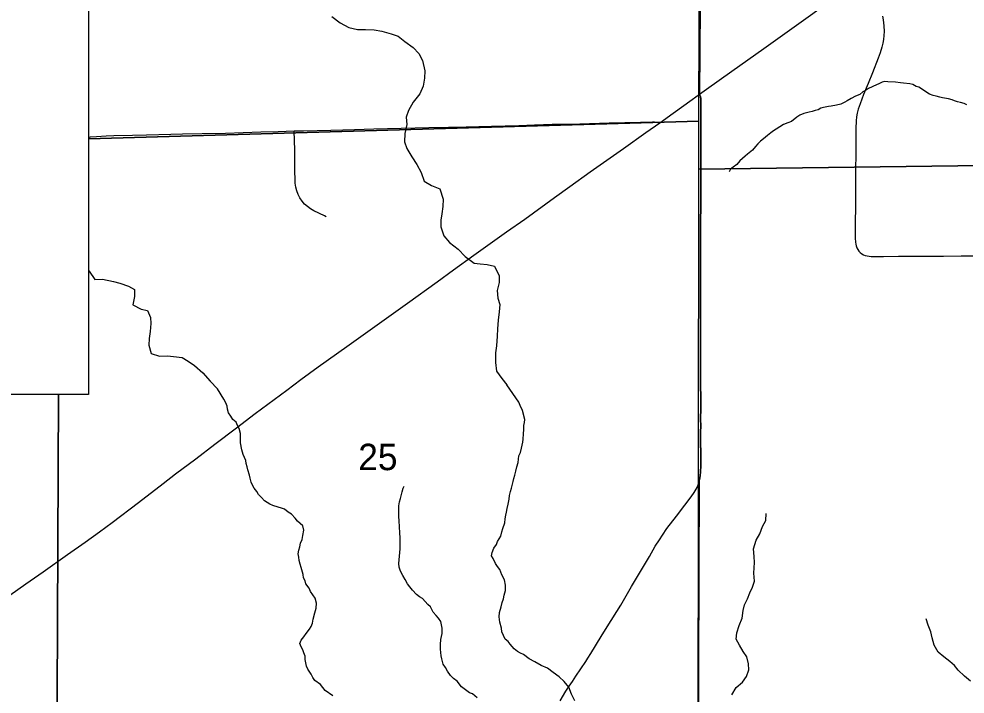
# Model space of a CAD drawing. Extents: x 0 to 34, y 0 to 22.
# Drawn here: x 4.694 to 6.195, y 16.396 to 17.466 of the extents above; entities that cross this region are included whole.
import ezdxf

# ---------------------------------------------------------------- set-up
doc = ezdxf.new("R2010")
doc.units = 0
for name, color, linetype in [('GM_X_County_Road', 7, 'Continuous'), ('GM_X_Minor_River', 7, 'Continuous'), ('GM_X_Section', 7, 'Continuous'), ('GM_X_Section_Text', 7, 'Continuous'), ('GM_X_State_Route', 7, 'Continuous'), ('GM_X_Township_Road', 7, 'Continuous'), ('SH_Text', 7, 'Continuous')]:
    doc.layers.add(name, color=color, linetype=linetype)

msp = doc.modelspace()

# ---------------------------------------------------------------- linework, layer by layer
at = {"layer": 'GM_X_County_Road'}
for points in [[(5.7756, 17.0016), (5.7756, 17.0136), (5.7756, 17.0291), (5.7756, 17.0416), (5.7756, 17.054), (5.7754, 17.0788), (5.7754, 17.0981), (5.7753, 17.1111), (5.7755, 17.1315), (5.7757, 17.1502), (5.776, 17.1626), (5.776, 17.1751), (5.7759, 17.1968), (5.7759, 17.2123), (5.7759, 17.2309), (5.7758, 17.2558), (5.776, 17.2689), (5.7761, 17.283), (5.7762, 17.309), (5.7759, 17.3389), (5.7754, 17.3427), (5.7746, 17.345), (5.7738, 17.3471)], [(5.5525, 16.3849), (5.5618, 16.4), (5.5671, 16.408), (5.5719, 16.4155), (5.5772, 16.4237), (5.5932, 16.447), (5.5965, 16.4522), (5.6015, 16.4601), (5.6175, 16.4866), (5.6272, 16.5024), (5.6488, 16.5368), (5.6658, 16.5659), (5.685, 16.5978), (5.6942, 16.6139), (5.7034, 16.6299), (5.71, 16.6402), (5.7147, 16.6478), (5.7219, 16.6579), (5.7369, 16.6776), (5.7504, 16.695), (5.7605, 16.7083), (5.7654, 16.715), (5.7685, 16.7204), (5.7699, 16.7232), (5.7722, 16.7291), (5.7734, 16.7337), (5.7738, 16.7352), (5.7749, 16.7414), (5.7756, 16.7476), (5.7759, 16.757), (5.7758, 16.7756), (5.7758, 16.7819), (5.7755, 16.7899), (5.7755, 16.7965), (5.7757, 16.8028), (5.7756, 16.8095), (5.7758, 16.8214), (5.7756, 16.8299), (5.7756, 16.8369), (5.7758, 16.8428), (5.7758, 16.849), (5.7758, 16.8614), (5.7757, 16.8893), (5.7757, 16.9111), (5.7755, 16.9546), (5.7756, 17.0016)]]:
    msp.add_lwpolyline(points, dxfattribs=at)
at = {"layer": 'GM_X_Minor_River'}
for points in [[(5.1905, 17.4701), (5.2034, 17.4604), (5.2171, 17.4529), (5.2311, 17.4495), (5.2436, 17.4496), (5.2576, 17.4493), (5.2697, 17.4471), (5.2845, 17.443), (5.2955, 17.4389), (5.3062, 17.4306), (5.3195, 17.4212), (5.3283, 17.4114), (5.3344, 17.4008), (5.3379, 17.3841), (5.3372, 17.3724), (5.335, 17.3599), (5.3301, 17.3477), (5.3196, 17.3344), (5.3121, 17.3214), (5.308, 17.3108), (5.3092, 17.299), (5.3059, 17.2846), (5.3055, 17.2717), (5.3094, 17.2611), (5.3174, 17.2475), (5.3254, 17.2354), (5.3319, 17.2229), (5.3366, 17.2093), (5.3483, 17.2022), (5.3616, 17.1969), (5.367, 17.1806), (5.3663, 17.1689), (5.3649, 17.1575), (5.3634, 17.1472), (5.3635, 17.1366), (5.3681, 17.1226), (5.3772, 17.112), (5.3906, 17.1015), (5.4016, 17.0894), (5.4161, 17.0793), (5.4259, 17.0782), (5.4369, 17.0771), (5.4483, 17.0742), (5.4559, 17.059), (5.4556, 17.0484), (5.4527, 17.0359), (5.4539, 17.0234), (5.4566, 17.0135), (5.4559, 17.0021), (5.4541, 16.9885), (5.4534, 16.9748), (5.4527, 16.9631), (5.4516, 16.9479), (5.4502, 16.9369), (5.4499, 16.9213), (5.4518, 16.9077), (5.4599, 16.8963), (5.4682, 16.8862)], [(6.198, 17.33), (6.1934, 17.3323), (6.1877, 17.3341), (6.1831, 17.3352), (6.1785, 17.3366), (6.1743, 17.3381), (6.1686, 17.3399), (6.159, 17.3413), (6.1552, 17.3424), (6.1491, 17.3442), (6.1445, 17.3449), (6.1388, 17.3471), (6.1216, 17.3583), (6.1174, 17.3593), (6.112, 17.3623), (6.1074, 17.3634), (6.0975, 17.3648), (6.0926, 17.3651), (6.0846, 17.3661), (6.0724, 17.3667), (6.0678, 17.367), (6.0636, 17.3662), (6.0584, 17.3635), (6.0546, 17.3619), (6.0417, 17.3561), (6.0372, 17.353), (6.033, 17.3506), (6.0281, 17.3468), (6.0213, 17.344), (6.0142, 17.3405), (6.0081, 17.3366), (6.0043, 17.3347), (5.9979, 17.3315), (5.9911, 17.3299), (5.9827, 17.3283), (5.9782, 17.3275), (5.9706, 17.3259), (5.9664, 17.3247), (5.9619, 17.3223), (5.9574, 17.3211), (5.9524, 17.3195), (5.9479, 17.3187), (5.9433, 17.3175), (5.9392, 17.3163), (5.9331, 17.314), (5.9282, 17.3105), (5.9196, 17.3039), (5.9139, 17.3019), (5.9067, 17.2988), (5.8954, 17.2918), (5.8912, 17.2891), (5.8867, 17.286), (5.8814, 17.2817), (5.8754, 17.2763), (5.8705, 17.2725), (5.8664, 17.2686), (5.8623, 17.264), (5.8578, 17.2583), (5.8499, 17.2521), (5.8461, 17.2486), (5.8378, 17.2413), (5.833, 17.2355)], [(5.833, 17.2355), (5.8273, 17.2316), (5.8228, 17.2282), (5.8209, 17.224)], [(4.804, 17.0684), (4.8052, 17.0662), (4.814, 17.053), (4.8265, 17.0538), (4.844, 17.0501), (4.8538, 17.0475), (4.8675, 17.0427), (4.8774, 17.0371), (4.8774, 17.0261), (4.8745, 17.0131), (4.8877, 17.006), (4.8976, 17.0038), (4.9026, 16.9928), (4.903, 16.9833), (4.9023, 16.9704), (4.9005, 16.9594), (4.8998, 16.9488), (4.9037, 16.9356), (4.9169, 16.9315), (4.9298, 16.9319), (4.9393, 16.9312), (4.9526, 16.9294), (4.9621, 16.9238), (4.9723, 16.9166), (4.9856, 16.9049), (4.9975, 16.8917), (5.0087, 16.8795)], [(5.1917, 16.3926), (5.1799, 16.4014), (5.1722, 16.4109), (5.1634, 16.417), (5.16, 16.4219), (5.1573, 16.4272), (5.1523, 16.4352), (5.15, 16.4398), (5.1481, 16.4504), (5.1481, 16.4558), (5.1458, 16.4611), (5.1442, 16.4656), (5.1415, 16.4702), (5.1396, 16.4755), (5.1415, 16.4809), (5.1457, 16.4862), (5.1495, 16.4915), (5.1548, 16.4983), (5.1575, 16.5029), (5.1594, 16.5078), (5.1609, 16.5143), (5.1635, 16.5242), (5.1654, 16.5318), (5.1658, 16.5398), (5.1639, 16.5478), (5.1604, 16.5531), (5.1562, 16.558), (5.1543, 16.5634), (5.1489, 16.5706), (5.1478, 16.5752), (5.1455, 16.5801), (5.1447, 16.585), (5.1416, 16.5965), (5.1401, 16.6018), (5.1385, 16.6075), (5.1378, 16.6128), (5.137, 16.6178), (5.1377, 16.6238), (5.1396, 16.6292), (5.1408, 16.6349), (5.143, 16.6406), (5.1445, 16.647), (5.1457, 16.6554), (5.1441, 16.6626), (5.1357, 16.6698), (5.1319, 16.6748), (5.1262, 16.6809), (5.1212, 16.6843), (5.1154, 16.6889), (5.1105, 16.6904), (5.1051, 16.6919), (5.0967, 16.6946), (5.0921, 16.6965), (5.0837, 16.7018), (5.0788, 16.7071), (5.0742, 16.7121), (5.0711, 16.717), (5.0669, 16.7224), (5.0642, 16.7269), (5.0623, 16.7315), (5.0608, 16.738), (5.0596, 16.7425), (5.0569, 16.7513), (5.0561, 16.7558), (5.0546, 16.7615), (5.0538, 16.7661), (5.0519, 16.7707), (5.0496, 16.7756), (5.0477, 16.7832), (5.0454, 16.7939), (5.0453, 16.8087), (5.0434, 16.8167), (5.0407, 16.8216), (5.0384, 16.827), (5.0334, 16.8311), (5.03, 16.8361), (5.0262, 16.8414), (5.025, 16.8475), (5.0242, 16.8521), (5.0223, 16.8574), (5.0192, 16.8631), (5.0087, 16.8795)], [(5.4461, 16.6104), (5.4438, 16.6149), (5.4446, 16.6203), (5.4472, 16.6271), (5.4518, 16.6328), (5.4533, 16.6373), (5.4582, 16.646), (5.4601, 16.6529), (5.4616, 16.6582), (5.4646, 16.6673), (5.4654, 16.6734), (5.4665, 16.6791), (5.4673, 16.684), (5.4684, 16.6901), (5.4699, 16.6969), (5.4714, 16.7045), (5.4721, 16.7106), (5.4736, 16.7167), (5.4755, 16.7224), (5.4782, 16.7326), (5.4789, 16.7375), (5.4804, 16.7425), (5.4823, 16.7489), (5.4838, 16.7558), (5.4861, 16.7626), (5.4872, 16.7732), (5.4895, 16.7785), (5.4914, 16.7854), (5.4921, 16.7903), (5.4932, 16.7949), (5.494, 16.7998), (5.4943, 16.8081), (5.4947, 16.815), (5.4947, 16.8214), (5.4962, 16.8264), (5.4966, 16.8313), (5.4927, 16.8454), (5.4893, 16.8534), (5.487, 16.8584), (5.4682, 16.8862)], [(5.4207, 16.3898), (5.4134, 16.3959), (5.4088, 16.3974), (5.3958, 16.4069), (5.389, 16.4161), (5.3836, 16.4203), (5.3786, 16.4252), (5.3737, 16.4317), (5.3706, 16.4374), (5.3671, 16.4427), (5.3648, 16.4514), (5.3637, 16.456), (5.3629, 16.4667), (5.3625, 16.4739), (5.3632, 16.4822), (5.3651, 16.4918), (5.3651, 16.5001), (5.3635, 16.5104), (5.3597, 16.5157), (5.3559, 16.5203), (5.3513, 16.5256), (5.3471, 16.534), (5.3425, 16.5378), (5.3341, 16.5469), (5.3295, 16.5496), (5.3245, 16.5534), (5.3184, 16.5602), (5.3138, 16.5656), (5.3104, 16.5705), (5.3065, 16.577), (5.3031, 16.5834), (5.2992, 16.5903), (5.2973, 16.5967), (5.2965, 16.6028), (5.2977, 16.6142), (5.2988, 16.626), (5.2987, 16.6431), (5.298, 16.6515), (5.2979, 16.6606), (5.2971, 16.6701), (5.2967, 16.677), (5.2967, 16.6941), (5.2978, 16.7006), (5.299, 16.7055), (5.3009, 16.712), (5.302, 16.7165), (5.3035, 16.7219), (5.3049, 16.7252)], [(5.8252, 16.3944), (5.832, 16.4057), (5.8419, 16.4144), (5.848, 16.4235), (5.8518, 16.4341), (5.8515, 16.4436), (5.8488, 16.4546), (5.8428, 16.463), (5.8372, 16.4729), (5.8316, 16.4824), (5.8327, 16.4926), (5.8366, 16.5044), (5.8411, 16.5157), (5.8427, 16.5279), (5.845, 16.5373), (5.85, 16.5468), (5.8534, 16.5563), (5.858, 16.5653), (5.861, 16.5744), (5.8599, 16.5873), (5.8608, 16.6044), (5.8604, 16.6139), (5.8593, 16.6257), (5.8635, 16.6397), (5.8693, 16.6499), (5.8738, 16.6613), (5.8788, 16.6711), (5.8796, 16.6821)], [(5.5032, 16.4513), (5.4946, 16.4582), (5.4896, 16.4605), (5.485, 16.4632), (5.4797, 16.4674), (5.4732, 16.4746), (5.4701, 16.4791), (5.4655, 16.4826), (5.4628, 16.4883), (5.4601, 16.4944), (5.4594, 16.5001), (5.457, 16.5096), (5.4559, 16.5179), (5.4562, 16.5248), (5.4589, 16.5339), (5.4608, 16.5408), (5.4627, 16.5465), (5.4638, 16.5522), (5.4661, 16.5598), (5.4661, 16.5681), (5.4641, 16.5765), (5.4599, 16.5849), (5.4568, 16.5929), (5.4534, 16.5978), (5.45, 16.6024), (5.4461, 16.6104)], [(6.2034, 16.4161), (6.1943, 16.4241), (6.1842, 16.4332), (6.1782, 16.4408), (6.171, 16.4473), (6.1612, 16.4546), (6.1521, 16.4622), (6.1458, 16.4729), (6.1428, 16.4847), (6.1405, 16.4945), (6.1364, 16.5048), (6.1331, 16.5147)], [(5.5756, 16.3846), (5.5707, 16.3956), (5.5662, 16.4066), (5.559, 16.4154), (5.5508, 16.4226), (5.5417, 16.4299), (5.5323, 16.4368), (5.5225, 16.441), (5.5123, 16.4464), (5.5032, 16.4513)]]:
    msp.add_lwpolyline(points, dxfattribs=at)
at = {"layer": 'GM_X_Section'}
for points in [[(4.804, 17.2765), (5.7727, 17.3042), (5.7758, 18.2578), (5.7756, 18.2855), (4.7762, 18.2959), (4.7636, 17.5881), (4.804, 17.5881)], [(5.7758, 18.2578), (6.9105, 18.2623), (6.9237, 17.2428), (5.7724, 17.2281), (5.7727, 17.3042)], [(4.7564, 16.8709), (4.754, 16.2718), (5.7718, 16.2797), (5.7724, 17.2281), (5.7727, 17.3042), (4.804, 17.2765), (4.804, 16.8709)], [(5.7724, 17.2281), (6.9237, 17.2428), (6.9303, 16.2282), (5.7699, 16.2149), (5.7718, 16.2797)], [(3.7435, 16.8709), (3.7413, 16.2718), (4.754, 16.2718), (4.7564, 16.8709)]]:
    msp.add_lwpolyline(points, close=True, dxfattribs=at)
at = {"layer": 'GM_X_State_Route'}
for points in [[(5.7738, 17.3471), (5.7846, 17.3549), (5.8251, 17.3837), (5.8757, 17.4196), (5.946, 17.4698), (5.9838, 17.4971), (5.9945, 17.5049), (6.0036, 17.5117), (6.0066, 17.514), (6.0098, 17.5165), (6.0233, 17.5278), (6.0271, 17.5311), (6.0418, 17.5443), (6.0552, 17.5567), (6.0732, 17.5733), (6.0998, 17.5976), (6.1187, 17.6149)], [(4.6669, 16.5434), (4.705, 16.5703), (4.7323, 16.5895), (4.771, 16.6167), (4.799, 16.6365), (4.8218, 16.6527), (4.8418, 16.6675), (4.8835, 16.6995), (4.9226, 16.7295), (4.9425, 16.7447), (4.9743, 16.7688), (5.0047, 16.7918), (5.0389, 16.8177), (5.0687, 16.8404), (5.0989, 16.863), (5.1187, 16.8778), (5.141, 16.8946), (5.1686, 16.9147), (5.2142, 16.9471), (5.3102, 17.0156), (5.3573, 17.0497), (5.3835, 17.0685), (5.4157, 17.0916), (5.4675, 17.1286), (5.4963, 17.149), (5.5438, 17.1832), (5.5679, 17.2005), (5.6004, 17.2237), (5.6533, 17.2608), (5.6886, 17.2862), (5.7105, 17.3018), (5.7317, 17.3169), (5.7619, 17.3386), (5.7738, 17.3471)]]:
    msp.add_lwpolyline(points, dxfattribs=at)
at = {"layer": 'GM_X_Township_Road'}
for points in [[(5.7807, 18.2409), (5.7736, 17.3477), (5.7744, 17.3455), (5.7752, 17.3432), (5.7757, 17.3395), (5.7759, 17.3096), (5.7759, 17.2835), (5.7758, 17.2694), (5.7756, 17.2563), (5.7757, 17.2315), (5.7757, 17.2129), (5.7757, 17.1973), (5.7758, 17.1756), (5.7758, 17.1632), (5.7755, 17.1508), (5.7753, 17.1321), (5.775, 17.1116), (5.7752, 17.0987), (5.7752, 17.0794), (5.7754, 17.0545), (5.7754, 17.0421), (5.7754, 17.0297), (5.7754, 17.0142), (5.7753, 16.9551), (5.7755, 16.9116), (5.7755, 16.8899), (5.7756, 16.8619), (5.7756, 16.8496), (5.7756, 16.8434), (5.7754, 16.8375), (5.7754, 16.8304), (5.7756, 16.8219), (5.7754, 16.81), (5.7755, 16.8034), (5.7753, 16.7971), (5.7753, 16.7904), (5.7756, 16.7824), (5.7756, 16.7762), (5.7757, 16.7575), (5.7753, 16.7482), (5.7747, 16.7419), (5.7736, 16.7357), (5.7732, 16.7342), (5.7682, 15.4021)], [(5.7682, 15.4021), (5.7732, 16.7342), (5.7736, 16.7357), (5.7747, 16.7419), (5.7753, 16.7482), (5.7757, 16.7575), (5.7756, 16.7762), (5.7756, 16.7824), (5.7753, 16.7904), (5.7753, 16.7971), (5.7755, 16.8034), (5.7754, 16.81), (5.7756, 16.8219), (5.7754, 16.8304), (5.7754, 16.8375), (5.7756, 16.8434), (5.7756, 16.8496), (5.7756, 16.8619), (5.7755, 16.8899), (5.7755, 16.9116), (5.7753, 16.9551), (5.7754, 17.0142), (5.7754, 17.0297), (5.7754, 17.0421), (5.7754, 17.0545), (5.7752, 17.0794), (5.7752, 17.0987), (5.775, 17.1116), (5.7753, 17.1321), (5.7755, 17.1508), (5.7758, 17.1632), (5.7758, 17.1756), (5.7757, 17.1973), (5.7757, 17.2129), (5.7757, 17.2315), (5.7756, 17.2563), (5.7758, 17.2694), (5.7759, 17.2835), (5.7759, 17.3096), (5.7757, 17.3395), (5.7752, 17.3432), (5.7744, 17.3455), (5.7736, 17.3477), (5.7807, 18.2409)], [(6.0642, 17.4711), (6.0652, 17.465), (6.0662, 17.4557), (6.0665, 17.4464), (6.0663, 17.4402), (6.0656, 17.434), (6.0646, 17.4279), (6.0631, 17.4218), (6.0604, 17.4129), (6.0572, 17.4041), (6.0481, 17.381), (6.0411, 17.3638), (6.0341, 17.3464), (6.0285, 17.332), (6.0255, 17.3232), (6.0239, 17.3172), (6.0227, 17.3111), (6.0221, 17.3049), (6.0216, 17.2925), (6.0218, 17.2583), (6.0213, 17.2211), (6.0212, 17.1745), (6.0207, 17.1372), (6.0207, 17.1186), (6.0212, 17.1124), (6.0217, 17.1093), (6.0224, 17.1063), (6.0235, 17.1034), (6.0248, 17.1006), (6.0265, 17.098), (6.0286, 17.0958), (6.0311, 17.0939), (6.0338, 17.0924), (6.0367, 17.0913), (6.0397, 17.0905), (6.0427, 17.09), (6.0459, 17.0898), (6.0521, 17.0896), (6.0656, 17.0897), (6.0894, 17.09), (6.1205, 17.09), (6.1391, 17.0901), (6.1608, 17.0903), (6.1888, 17.0905), (6.2166, 17.0908)], [(5.1307, 17.2889), (5.1451, 17.2888), (5.1887, 17.2898), (5.226, 17.2909), (5.257, 17.2919), (5.3005, 17.293), (5.3441, 17.2941), (5.3752, 17.295), (5.4032, 17.2955), (5.4436, 17.2966), (5.4871, 17.2977), (5.512, 17.2984), (5.54, 17.2993), (5.568, 17.2998), (5.6302, 17.3015), (5.6799, 17.3029), (5.6991, 17.3032), (5.7022, 17.303), (5.7042, 17.3027), (5.7105, 17.3018)], [(4.804, 17.2786), (4.8076, 17.2792), (4.8168, 17.2802), (4.8322, 17.2811), (4.8446, 17.2815), (4.8741, 17.2822), (4.8962, 17.2827), (4.935, 17.2837), (4.9533, 17.2841), (4.9843, 17.2845), (5.0216, 17.2854), (5.0774, 17.2872), (5.1054, 17.2879), (5.1307, 17.2889)], [(5.1813, 17.1526), (5.1786, 17.1541), (5.1618, 17.1619), (5.1565, 17.165), (5.1516, 17.1687), (5.147, 17.1728), (5.143, 17.1775), (5.1396, 17.1826), (5.1367, 17.1881), (5.1346, 17.1938), (5.133, 17.1998), (5.1322, 17.2059), (5.1319, 17.2121), (5.1318, 17.2244), (5.1314, 17.2583), (5.1307, 17.2889)]]:
    msp.add_lwpolyline(points, dxfattribs=at)
at = {"layer": 'SH_Text'}
msp.add_lwpolyline([(2.5841, 17.5881), (4.804, 17.5881), (4.804, 16.8709), (2.5841, 16.8709)], close=True, dxfattribs=at)

# ---------------------------------------------------------------- texts
at = {"layer": 'GM_X_Section_Text'}
msp.add_text('25', height=0.04186, rotation=0, dxfattribs=at).set_placement((5.2322, 16.7507))

doc.saveas('drawing.dxf')
